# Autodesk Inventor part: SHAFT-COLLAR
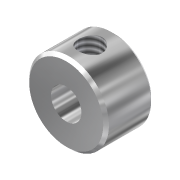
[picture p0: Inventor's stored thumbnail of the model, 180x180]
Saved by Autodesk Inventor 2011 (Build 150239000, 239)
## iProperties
Created: 2008-03
Part Number: SHAFT-COLLAR
Document SubType Name: Modeling
Density: 1 g/cm^3
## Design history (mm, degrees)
sketch "Sketch1"
  geometry: C1 r 5.499 at (-7.091, -3.091)
  constraints: 1 centre point
  dimensions: "d0" = 10.9982 diameter of C1
extrude "Extrusion1" new body sketch "Sketch1" distance "d1" = 6.604; taper "d2" = 0 deg
sketch "Sketch2"
  geometry: C1 r 5.499 at (0, 0) reference
hole "Hole1" sketch "Sketch2" at (0, 0) diameter "d3" = 4.191; stored, may be unused: countersink angle "d7" = 82 deg, drill point angle "d9" = 118 deg; dims "d4" = 12.7, "d5" = 9.525, "d6" = 6.35, "d8" = 19.05
workplane "Work Plane1"
sketch "Sketch3"
  geometry: L1 (-5.499, 0)-(5.499, 0) reference; L2 (-5.499, 0)-(-5.499, -6.604) reference; 3 further points
  constraints: 2 midpoint, 1 horizontal alignment, 1 vertical alignment
hole "Hole2" sketch "Sketch3" at (0, -3.302) diameter "d10" = 3.302; stored, may be unused: countersink angle "d14" = 82 deg, drill point angle "d16" = 118 deg; dims "d11" = 12.7, "d12" = 9.525, "d13" = 6.35, "d15" = 19.05
chamfer "Chamfer1" distance "d17" = 0.39687; stored, may be unused: second distance "d18" = 3.175, angle "d19" = 45 deg
body "Solid1"
node "Projected Loop1"
